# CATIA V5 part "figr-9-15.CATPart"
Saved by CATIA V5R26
Part number: Part1
Bounding box of the stored display mesh (mm): x -77.304 to 77.304, y -77.304 to 118.168, z 0 to 125
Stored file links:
  D:\_Deepak\CATIA\CATIA V5-6R2016_Deepak\Resources\Part files\Partfiles\c09_catia_v5_6r2016_prt\figr-9-15.CATPart
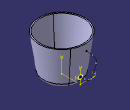
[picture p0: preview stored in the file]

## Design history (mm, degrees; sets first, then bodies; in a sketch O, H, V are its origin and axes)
Set1
  Plane1: type Normal, Curve Sketch3, RefPoint vertex of Sketch3
Body1 (main body)
  Sketch1 on yz-plane, origin (0, 0, 0), H (0, 1, 0), V (0, 0, 1)
    line L1 (0, 0) -> (60, 0)
    point P1 (60, 0)
    point P2 (60, 0)
    line L2 (60, 0) -> (77.5, 125)
    point P3 (77.5, 125)
    line L3 (77.5, 125) -> (0, 125)
    point P4 (0, 125)
    line L4 (0, 125) -> (0, 0)
    axis line L5 (0, 150.2858) -> (0, -31.0593)
    point P5 (0, 150.2858)
    radius about axis P1 L5 = 60
    radius about axis P3 L5 = 77.5
    distance L3 L1 = 125
    horizontal: L1 H, L3 H
    coincidence: P4 V, P2 P1, P5 V
    vertical: L4 V, L5 V
  Shaft1: profile Sketch1, axis Sketch1.L5, angle 360
  Fillet1: radius 15, on edge [face of Shaft1 | face of Shaft1]
  Shell1: ExtOffset 0, Face face of Shaft1, IntOffset 4
  Sketch2 on Plane1, origin (0, 62.9841, 0), H (-1, 0, 0), V (0, 0, 1)
    circle A1 centre (0, 22.002) radius 7.5
    reference projected point E1 (0, 22.002) from vertex of Sketch3
    radius A1 = 7.5
    concentricity: A1 E1
  Sketch3 on yz-plane, origin (0, 0, 0), H (0, 1, 0), V (0, 0, 1)
    line L1 (62.9841, 22.002) -> (78.2172, 22.002)
    arc A1 centre (78.2172, 44.1133) radius 22.1113 from (78.2172, 22.002) to (97.9307, 34.0988) ccw
    arc A2 centre (-112.3295, 140.9107) radius 235.8349 from (97.9307, 34.0988) to (117.8681, 89.6549) ccw
    arc A3 centre (104.0328, 92.7355) radius 14.1742 from (117.8681, 89.6549) to (104.4272, 106.9041) ccw
    arc A4 centre (93.6744, -279.4123) radius 386.4661 from (104.4272, 106.9041) to (82.9216, 106.9041) ccw
    horizontal: L1 H
    tangency: A1 L1, A2 A1, A3 A2, A4 A3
